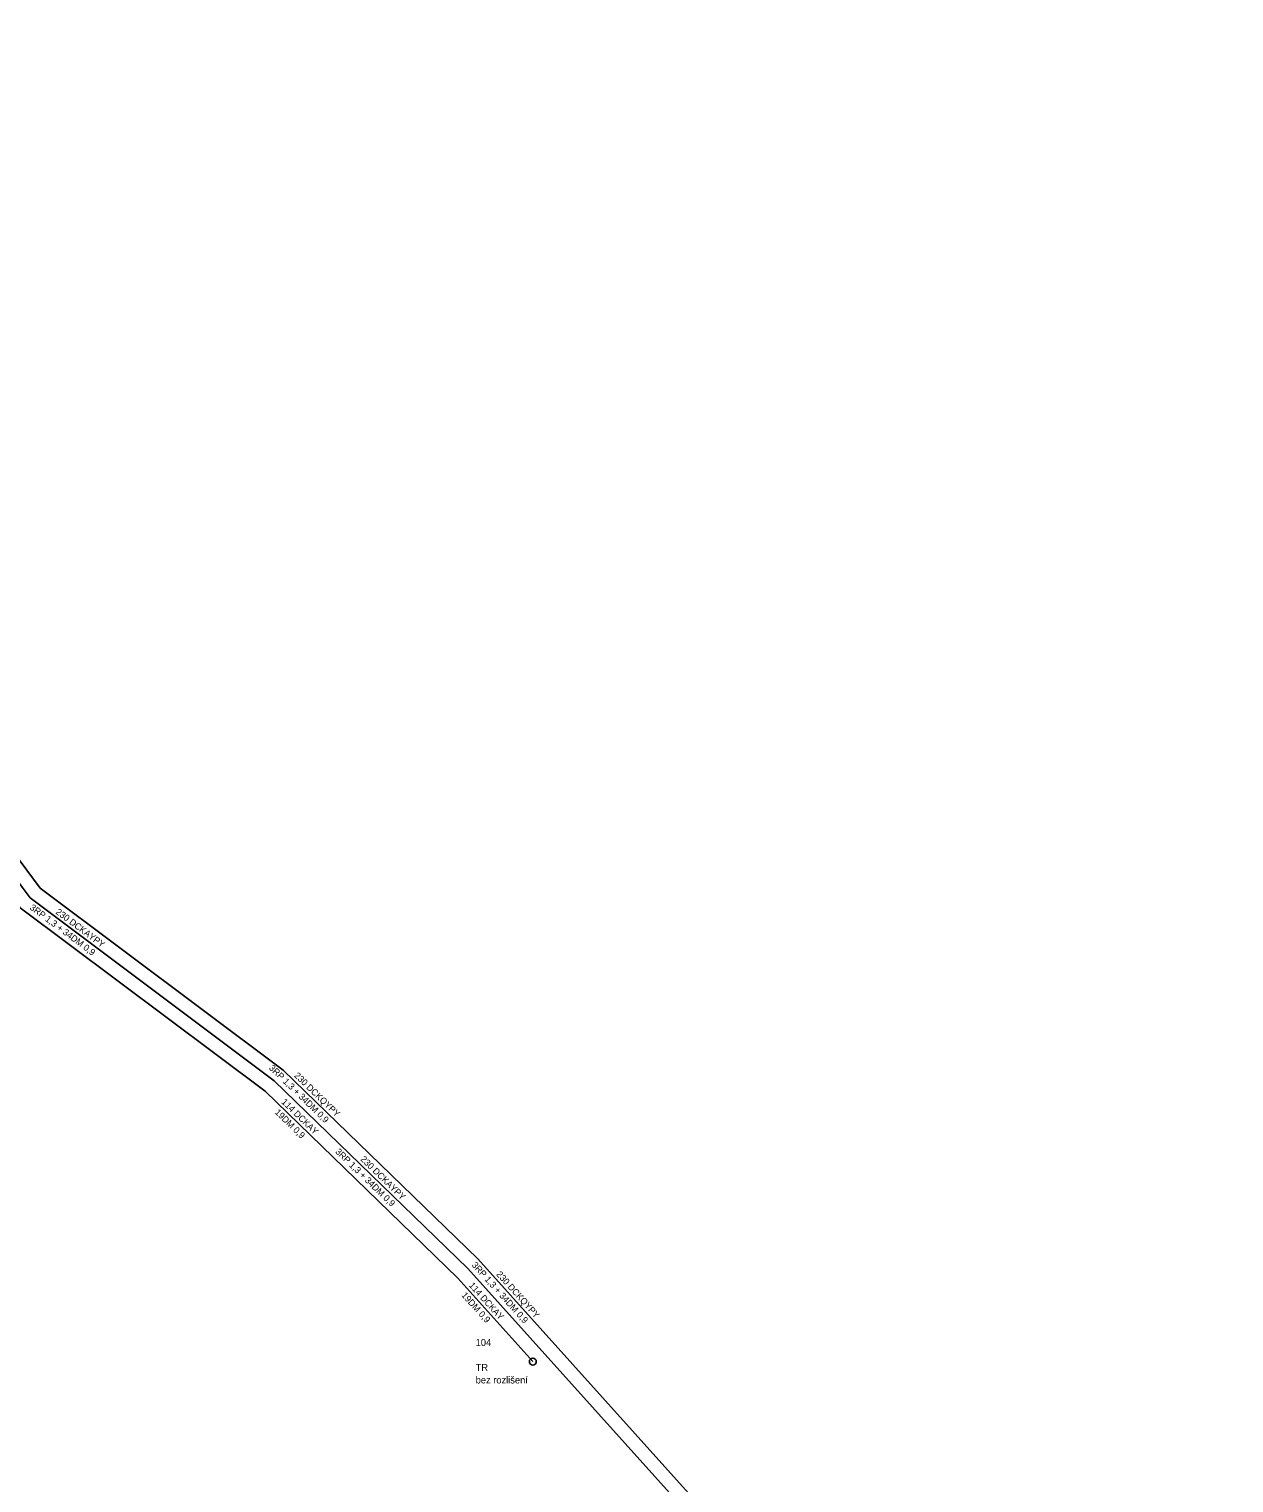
# Model space of a CAD drawing. Extents: x -756413 to -755757, y -1139003 to -1138237.
# Drawn here: x -756067.7 to -756002.7, y -1138514.9 to -1138436.5 of the extents above; entities that cross this region are included whole.
import ezdxf

# ---------------------------------------------------------------- set-up
doc = ezdxf.new("R2010")
doc.units = 0
for name, color, linetype in [('f307_kabel_metal', 7, 'Continuous'), ('f307_kabel_metal_ann', 7, 'Continuous'), ('f307_spojka_metal', 7, 'Continuous'), ('f307_spojka_metal_ann', 7, 'Continuous')]:
    doc.layers.add(name, color=color, linetype=linetype)

msp = doc.modelspace()

# ---------------------------------------------------------------- linework, layer by layer
at = {"layer": 'f307_kabel_metal'}
for points in [[(-756118.06, -1138436.494), (-756115.302, -1138439.6), (-756115.868, -1138440.078), (-756115.309, -1138440.722), (-756114.732, -1138441.187), (-756100.106, -1138453.248), (-756099.193, -1138453.958), (-756098.582, -1138454.396), (-756073.437, -1138474.323), (-756067.467, -1138482.356), (-756067.103, -1138482.845), (-756053.982, -1138492.668), (-756043.489, -1138502.85), (-756028.271, -1138519.778)], [(-756115.87, -1138441.22), (-756100.575, -1138453.833), (-756099.642, -1138454.559), (-756099.033, -1138454.995), (-756073.98, -1138474.85), (-756068.069, -1138482.803), (-756067.64, -1138483.38), (-756054.47, -1138493.24), (-756044.03, -1138503.37), (-756028.82, -1138520.29), (-756023.791, -1138525.491), (-756023.27, -1138526.03), (-756020.86, -1138528.62), (-756019.97, -1138529.61), (-756019.66, -1138535.02), (-756014.34, -1138539.73), (-756002.7, -1138549.54), (-756020.63, -1138568.61), (-756010.79, -1138582.3), (-756003.44, -1138591.94)], [(-756109.723, -1138449.702), (-756101.395, -1138453.937), (-756074.523, -1138475.377), (-756068.671, -1138483.25), (-756068.177, -1138483.915), (-756054.958, -1138493.812), (-756044.571, -1138503.89), (-756040.521, -1138508.396)]]:
    msp.add_lwpolyline(points, dxfattribs=at)
at = {"layer": 'f307_spojka_metal'}
msp.add_circle((-756040.521, -1138508.396), 0.188, dxfattribs=at)

# ---------------------------------------------------------------- texts
at = {"layer": 'f307_kabel_metal_ann'}
for s, rotation, p in [(' 3RP 1,3 + 34DM 0,9', 323.18, (-756067.799, -1138483.885)), ('230 DCKAYPY', 323.18, (-756066.297, -1138484.198)), (' 3RP 1,3 + 34DM 0,9', 315.86, (-756054.876, -1138492.497)), ('230 DCKQYPY', 315.86, (-756053.426, -1138492.999)), ('114 DCKAY', 315.87, (-756054.112, -1138494.424)), (' 19DM 0,9', 315.87, (-756054.565, -1138494.889)), (' 3RP 1,3 + 34DM 0,9', 315.86, (-756051.301, -1138497.011)), ('230 DCKAYPY', 315.86, (-756049.851, -1138497.513)), (' 3RP 1,3 + 34DM 0,9', 311.96, (-756043.93, -1138503.107)), ('230 DCKQYPY', 311.96, (-756042.518, -1138503.707)), ('114 DCKAY', 311.95, (-756043.998, -1138504.303)), (' 19DM 0,9', 311.95, (-756044.483, -1138504.736))]:
    msp.add_text(s, height=0.35, rotation=rotation, dxfattribs=at).set_placement(p)
at = {"layer": 'f307_spojka_metal_ann'}
for s, p in [('104', (-756043.606, -1138507.551)), ('TR', (-756043.606, -1138508.901)), ('bez rozlišení', (-756043.606, -1138509.576))]:
    msp.add_text(s, height=0.375, dxfattribs=at).set_placement(p)

doc.saveas('drawing.dxf')
